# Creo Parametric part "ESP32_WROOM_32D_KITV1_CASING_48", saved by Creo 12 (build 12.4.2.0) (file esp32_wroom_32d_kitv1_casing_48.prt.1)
Units: Custom; MM, KILOGRAM, SECS

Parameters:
  PTC_WM_ITERATION = "0"
  PTC_WM_VERSION = "-.0"
  PTC_WM_LIFECYCLE_STATE = "In Work"
  PTC_WM_LIFECYCLE = "MO_CADDocument"
  PTC_WM_CREATED_BY = "Maximilian Roepper (Z0017RMS: MO)"
  PTC_WM_CREATED_ON = "18-Sep-26 11:36:42 AM"
  PTC_WM_MODIFIED_BY = "Maximilian Roepper (Z0017RMS: MO)"
  PTC_WM_MODIFIED_ON = "18-Sep-26 11:36:46 AM"
  PDMLINKNUMBER = "PDM000071455205"
  PTC_WM_NAME = "esp32_wroom_32d_kitv1_casing_48.prt"
  PTC_WM_NUMBER = "PDM000071455205"

Other parameters: WEIGHT, WEIGHT_FACTOR, WEIGHT_ADD, _MASS_TEMP, _DIFF_TEMP, MC_ERRORS, SUPPLIER

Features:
  1. coordinate system
  2. datum plane "PRT_YZ"
  3. datum plane "PRT_XY"
  4. datum plane "PRT_XZ"
  5. coordinate system
  6. datum axis
  7. datum axis
  8. datum axis
  9. coordinate system
  10. imported feature
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
Other named items: PRT, SIEMENS_MO, DRW_VIEW_ORG, PRT_X, PRT_Y, PRT_Z, CS0, ROUGH_GROB

Layers: 00_STD_CSYS-KSYS, 01_STD_PLANES-EBENEN, 02_STD_AXES-ACHSEN, 03_STD_CSYS-KSYS, 24_IMPORT_FEAT-IMPORT_KE

Surfaces: 6 plane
